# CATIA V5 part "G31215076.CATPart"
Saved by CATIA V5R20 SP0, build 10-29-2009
Part number: G31215076
Revision: 5
Definition: design
Nomenclature: G31215076
Source: made
Description: NOT SPECIFIED
Bounding box of the stored display mesh (mm): x -6 to 76, y -12.31 to 12.31, z -12.5 to 12.5
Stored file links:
  C:\Users\Raffaele\Desktop\3D X SITO CF\BOLEX\23-BUSH REF 312\G31215076.CATPart

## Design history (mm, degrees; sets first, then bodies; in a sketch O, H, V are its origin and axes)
Body1 "MANIFOLD_SOLID_BREP #16915" (main body)
  Solid1: solid without history
Body2 "MANIFOLD_SOLID_BREP #17058"
  Solid2: solid without history
Body3 "MANIFOLD_SOLID_BREP #17201"
  Solid3: solid without history
Body4 "MANIFOLD_SOLID_BREP #17344"
  Solid4: solid without history
Body5 "MANIFOLD_SOLID_BREP #17487"
  Solid5: solid without history
Body6 "MANIFOLD_SOLID_BREP #17632"
  Solid6: solid without history
Body7 "MANIFOLD_SOLID_BREP #17777"
  Solid7: solid without history
Body8 "MANIFOLD_SOLID_BREP #17922"
  Solid8: solid without history
Body9 "MANIFOLD_SOLID_BREP #18067"
  Solid9: solid without history
Body10 "MANIFOLD_SOLID_BREP #18212"
  Solid10: solid without history
Body11 "MANIFOLD_SOLID_BREP #18357"
  Solid11: solid without history
Body12 "MANIFOLD_SOLID_BREP #18502"
  Solid12: solid without history
Body13 "MANIFOLD_SOLID_BREP #18647"
  Solid13: solid without history
Body14 "MANIFOLD_SOLID_BREP #18792"
  Solid14: solid without history
Body15 "MANIFOLD_SOLID_BREP #18937"
  Solid15: solid without history
Body16 "MANIFOLD_SOLID_BREP #19082"
  Solid16: solid without history
Body17 "MANIFOLD_SOLID_BREP #19227"
  Solid17: solid without history
Body18 "MANIFOLD_SOLID_BREP #19372"
  Solid18: solid without history
Body19 "MANIFOLD_SOLID_BREP #19517"
  Solid19: solid without history
Body20 "MANIFOLD_SOLID_BREP #19663"
  Solid20: solid without history
Body21 "MANIFOLD_SOLID_BREP #19808"
  Solid21: solid without history
Body22 "MANIFOLD_SOLID_BREP #19953"
  Solid22: solid without history
Body23 "MANIFOLD_SOLID_BREP #20099"
  Solid23: solid without history
Body24 "MANIFOLD_SOLID_BREP #20244"
  Solid24: solid without history
Body25 "MANIFOLD_SOLID_BREP #20389"
  Solid25: solid without history
Body26 "MANIFOLD_SOLID_BREP #20534"
  Solid26: solid without history
Body27 "MANIFOLD_SOLID_BREP #20679"
  Solid27: solid without history
Body28 "MANIFOLD_SOLID_BREP #20824"
  Solid28: solid without history
Body29 "MANIFOLD_SOLID_BREP #20969"
  Solid29: solid without history
Body30 "MANIFOLD_SOLID_BREP #21114"
  Solid30: solid without history
Body31 "MANIFOLD_SOLID_BREP #21259"
  Solid31: solid without history
Body32 "MANIFOLD_SOLID_BREP #21402"
  Solid32: solid without history
Body33 "MANIFOLD_SOLID_BREP #21545"
  Solid33: solid without history
Body34 "MANIFOLD_SOLID_BREP #21690"
  Solid34: solid without history
Body35 "MANIFOLD_SOLID_BREP #21835"
  Solid35: solid without history
Body36 "MANIFOLD_SOLID_BREP #21981"
  Solid36: solid without history
Body37 "MANIFOLD_SOLID_BREP #22126"
  Solid37: solid without history
Body38 "MANIFOLD_SOLID_BREP #22271"
  Solid38: solid without history
Body39 "MANIFOLD_SOLID_BREP #22417"
  Solid39: solid without history
Body40 "MANIFOLD_SOLID_BREP #22562"
  Solid40: solid without history
Body41 "MANIFOLD_SOLID_BREP #22707"
  Solid41: solid without history
Body42 "MANIFOLD_SOLID_BREP #22852"
  Solid42: solid without history
Body43 "MANIFOLD_SOLID_BREP #22997"
  Solid43: solid without history
Body44 "MANIFOLD_SOLID_BREP #23142"
  Solid44: solid without history
Body45 "MANIFOLD_SOLID_BREP #23287"
  Solid45: solid without history
Body46 "MANIFOLD_SOLID_BREP #23432"
  Solid46: solid without history
Body47 "MANIFOLD_SOLID_BREP #23577"
  Solid47: solid without history
Body48 "MANIFOLD_SOLID_BREP #23722"
  Solid48: solid without history
Body49 "MANIFOLD_SOLID_BREP #23867"
  Solid49: solid without history
Body50 "MANIFOLD_SOLID_BREP #24013"
  Solid50: solid without history
Body51 "MANIFOLD_SOLID_BREP #24158"
  Solid51: solid without history
Body52 "MANIFOLD_SOLID_BREP #24303"
  Solid52: solid without history
Body53 "MANIFOLD_SOLID_BREP #24449"
  Solid53: solid without history
Body54 "MANIFOLD_SOLID_BREP #24594"
  Solid54: solid without history
Body55 "MANIFOLD_SOLID_BREP #24739"
  Solid55: solid without history
Body56 "MANIFOLD_SOLID_BREP #24882"
  Solid56: solid without history
Body57 "MANIFOLD_SOLID_BREP #25025"
  Solid57: solid without history
Body58 "MANIFOLD_SOLID_BREP #25170"
  Solid58: solid without history
Body59 "MANIFOLD_SOLID_BREP #25315"
  Solid59: solid without history
Body60 "MANIFOLD_SOLID_BREP #25460"
  Solid60: solid without history
Body61 "MANIFOLD_SOLID_BREP #25605"
  Solid61: solid without history
Body62 "MANIFOLD_SOLID_BREP #25750"
  Solid62: solid without history
Body63 "MANIFOLD_SOLID_BREP #25895"
  Solid63: solid without history
Body64 "MANIFOLD_SOLID_BREP #26038"
  Solid64: solid without history
Body65 "MANIFOLD_SOLID_BREP #26181"
  Solid65: solid without history
Body66 "MANIFOLD_SOLID_BREP #26326"
  Solid66: solid without history
Body67 "MANIFOLD_SOLID_BREP #26471"
  Solid67: solid without history
Body68 "MANIFOLD_SOLID_BREP #26617"
  Solid68: solid without history
Body69 "MANIFOLD_SOLID_BREP #26762"
  Solid69: solid without history
Body70 "MANIFOLD_SOLID_BREP #26907"
  Solid70: solid without history
Body71 "MANIFOLD_SOLID_BREP #27053"
  Solid71: solid without history
Body72 "MANIFOLD_SOLID_BREP #27198"
  Solid72: solid without history
Body73 "MANIFOLD_SOLID_BREP #27343"
  Solid73: solid without history
Body74 "MANIFOLD_SOLID_BREP #27488"
  Solid74: solid without history
Body75 "MANIFOLD_SOLID_BREP #27633"
  Solid75: solid without history
Body76 "MANIFOLD_SOLID_BREP #27778"
  Solid76: solid without history
Body77 "MANIFOLD_SOLID_BREP #27923"
  Solid77: solid without history
Body78 "MANIFOLD_SOLID_BREP #28068"
  Solid78: solid without history
Body79 "MANIFOLD_SOLID_BREP #28213"
  Solid79: solid without history
Body80 "MANIFOLD_SOLID_BREP #28358"
  Solid80: solid without history
Body81 "MANIFOLD_SOLID_BREP #28503"
  Solid81: solid without history
Body82 "MANIFOLD_SOLID_BREP #28649"
  Solid82: solid without history
Body83 "MANIFOLD_SOLID_BREP #28794"
  Solid83: solid without history
Body84 "MANIFOLD_SOLID_BREP #28939"
  Solid84: solid without history
Body85 "MANIFOLD_SOLID_BREP #29085"
  Solid85: solid without history
Body86 "MANIFOLD_SOLID_BREP #29230"
  Solid86: solid without history
Body87 "MANIFOLD_SOLID_BREP #29375"
  Solid87: solid without history
Body88 "MANIFOLD_SOLID_BREP #29518"
  Solid88: solid without history
Body89 "MANIFOLD_SOLID_BREP #29661"
  Solid89: solid without history
Body90 "MANIFOLD_SOLID_BREP #29806"
  Solid90: solid without history
Body91 "MANIFOLD_SOLID_BREP #29951"
  Solid91: solid without history
Body92 "MANIFOLD_SOLID_BREP #30096"
  Solid92: solid without history
Body93 "MANIFOLD_SOLID_BREP #30241"
  Solid93: solid without history
Body94 "MANIFOLD_SOLID_BREP #30386"
  Solid94: solid without history
Body95 "MANIFOLD_SOLID_BREP #30531"
  Solid95: solid without history
Body96 "MANIFOLD_SOLID_BREP #30674"
  Solid96: solid without history
Body97 "MANIFOLD_SOLID_BREP #30817"
  Solid97: solid without history
Body98 "MANIFOLD_SOLID_BREP #30962"
  Solid98: solid without history
Body99 "MANIFOLD_SOLID_BREP #31107"
  Solid99: solid without history
Body100 "MANIFOLD_SOLID_BREP #31253"
  Solid100: solid without history
Body101 "MANIFOLD_SOLID_BREP #31398"
  Solid101: solid without history
Body102 "MANIFOLD_SOLID_BREP #31543"
  Solid102: solid without history
Body103 "MANIFOLD_SOLID_BREP #31689"
  Solid103: solid without history
Body104 "MANIFOLD_SOLID_BREP #31834"
  Solid104: solid without history
Body105 "MANIFOLD_SOLID_BREP #31979"
  Solid105: solid without history
Body106 "MANIFOLD_SOLID_BREP #32124"
  Solid106: solid without history
Body107 "MANIFOLD_SOLID_BREP #32269"
  Solid107: solid without history
Body108 "MANIFOLD_SOLID_BREP #32414"
  Solid108: solid without history
Body109 "MANIFOLD_SOLID_BREP #32559"
  Solid109: solid without history
Body110 "MANIFOLD_SOLID_BREP #32704"
  Solid110: solid without history
Body111 "MANIFOLD_SOLID_BREP #32849"
  Solid111: solid without history
Body112 "MANIFOLD_SOLID_BREP #32992"
  Solid112: solid without history
Body113 "MANIFOLD_SOLID_BREP #33135"
  Solid113: solid without history
Body114 "MANIFOLD_SOLID_BREP #33280"
  Solid114: solid without history
Body115 "MANIFOLD_SOLID_BREP #33425"
  Solid115: solid without history
Body116 "MANIFOLD_SOLID_BREP #33571"
  Solid116: solid without history
Body117 "MANIFOLD_SOLID_BREP #33716"
  Solid117: solid without history
Body118 "MANIFOLD_SOLID_BREP #33861"
  Solid118: solid without history
Body119 "MANIFOLD_SOLID_BREP #34007"
  Solid119: solid without history
Body120 "MANIFOLD_SOLID_BREP #34152"
  Solid120: solid without history
Body121 "MANIFOLD_SOLID_BREP #34297"
  Solid121: solid without history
